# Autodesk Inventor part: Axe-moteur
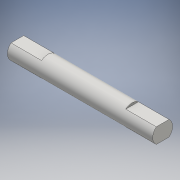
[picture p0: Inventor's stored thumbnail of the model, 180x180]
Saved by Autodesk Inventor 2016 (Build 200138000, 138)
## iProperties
Created: 2018-03
Part Number: Axe-moteur
Material: Plastique ABS
Document SubType Name: Modeling
Designer: Bruno
Density: 1.06 g/cm^3
Appearance: Lisse - Blanc
Author: Bruno
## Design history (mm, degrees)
sketch "Esquisse1"
  geometry: C1 r 2.6 at (0, 0); 1 further point
  constraints: 1 centre point, 1 coincident
  dimensions: "d0" = 5.2 diameter of C1
extrude "Extrusion1" new body sketch "Esquisse1" distance "d1" = 9; taper "d2" = 0 deg
sketch "Esquisse2"
  geometry: L1 (-2.458, 3.759)-(-2.458, -4.145); L2 (2, 4.867)-(6.145, 4.867); L3 (6.145, 4.867)-(6.145, -5.928); L4 (6.145, -5.928)-(2, -5.928); L5 (2, -5.928)-(2, 4.867); L6 (-5.181, 5.157)-(-2, 5.157); L7 (-2, 5.157)-(-2, -5.253); L8 (-2, -5.253)-(-5.181, -5.253); L9 (-5.181, -5.253)-(-5.181, 5.157); 1 further point
  constraints: 18 end point, 4 parallel, 2 horizontal, 2 perpendicular, 1 vertical
  dimensions: "d3" = 4 distance between parallel lines of L5 L7; "d4" = 2 distance from line of L5 point (0, 0)
extrude "Extrusion2" cut sketch "Esquisse2" distance "d5" = 8; taper "d6" = 0 deg
sketch "Esquisse3"
  geometry: C1 r 2.6 at (0, 0) reference; 1 further point
extrude "Extrusion3" join sketch "Esquisse3" distance "d7" = 10; taper "d8" = 0 deg
mirror "Symétrie1"
node "Solide1"
node "Boucle projetée1"
